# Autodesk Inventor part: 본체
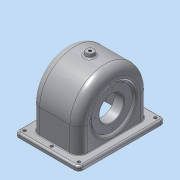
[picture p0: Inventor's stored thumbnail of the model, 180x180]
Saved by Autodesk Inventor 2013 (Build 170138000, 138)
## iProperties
Created: 2015-09
Part Number: 본체
Material: 알루미늄 6061
Document SubType Name: Modeling
Designer: dgall
Density: 1 g/cm^3
Author: dgall
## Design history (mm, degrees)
sketch "스케치1"
  geometry: L1 (-52, 70)-(52, 70); L2 (52, 70)-(52, -70); L3 (52, -70)-(-52, -70); L4 (-52, -70)-(-52, 70); 3 further points
  constraints: 8 end point, 2 midpoint, 2 parallel, 1 horizontal, 1 horizontal alignment, 1 perpendicular, 1 vertical alignment
  dimensions: "d0" = 104 distance of L1.start L1.end; "d2" = 140 distance of L1.end L2.end
extrude "돌출1" new body sketch "스케치1" distance "d3" = 7; taper "d4" = 0 deg
sketch "스케치2"
  geometry: L1 (70, 7)-(-70, 7) reference; L2 (-57, 7)-(-57, 47); L3 (57, 47)-(57, 7); L4 (-70, 0)-(70, 0) reference; A1 r 57 centre (0, 47) between (57, 47) and (-57, 47); 1 further point
  constraints: 4 end point, 2 perpendicular, 2 point on circle, 2 point on line, 2 tangent, 1 centre point, 1 vertical alignment
  dimensions: "d5" = 47 distance of point (0, 0) A1.centre; "d39" = 104 dimension on A1 L4
extrude "돌출2" join sketch "스케치2" stored distance "d7" = 77; taper "d8" = 0 deg
sketch "스케치3"
  geometry: L1 (-57, 7)-(-57, 47) reference; L2 (57, 47)-(57, 7) reference; L3 (-51, 0)-(-51, 47); L4 (51, 47)-(51, 0); L5 (-70, 0)-(70, 0) reference; A1 r 57 centre (0, 47) between (57, 47) and (-57, 47) reference; A2 r 51 centre (0, 47) between (51, 47) and (-51, 47); 1 further point
  constraints: 4 end point, 2 point on circle, 2 point on line, 1 centre point
  dimensions: "d9" = 6 radial gap between concentric circles of A2 A1; "d10" = 6 distance between parallel lines of L3 L1; "d11" = 6 distance between parallel lines of L2 L4
extrude "돌출3" cut sketch "스케치3" stored distance "d12" = 67; taper "d13" = 0 deg
sketch "스케치4"
  geometry: C1 r 31 at (47, 0); A1 r 57 centre (47, 0) between (47, -57) and (47, 57) reference; 1 further point
  constraints: 1 centre point, 1 coincident
  dimensions: "d14" = 62 diameter of C1
extrude "돌출4" join sketch "스케치4" distance "d16" = 10; taper "d17" = 0 deg
sketch "스케치6"
  geometry: C1 r 37.5 at (-47, 0); A1 r 57 centre (-47, 0) between (-47, 57) and (-47, -57) reference; 1 further point
  constraints: 1 centre point, 1 coincident
  dimensions: "d27" = 75 diameter of C1
extrude "돌출5" cut sketch "스케치6" distance "d29" = 5; taper "d30" = 0 deg
sketch "스케치7"
  geometry: L1 (-38.5, 104)-(-38.5, 47) reference; L2 (38.5, 47)-(38.5, 104) reference; L3 (-38.5, 47)-(38.5, 47); L4 (-38.5, 90.943)-(-19.5, 75); L5 (-19.5, 75)-(-19.5, 47); L6 (-35.5, 80)-(-35.5, 47); L7 (-38.5, 84.416)-(-33.237, 80); L8 (-33.237, 80)-(-35.5, 80); 1 further point
  constraints: 12 end point, 4 perpendicular, 4 point on line, 1 parallel
  dimensions: "d31" = 3 distance between parallel lines of L6 L1; "d32" = 16 distance between parallel lines of L5 L6; "d33" = 50 deg angle of L5 L4; "d34" = 56 diameter of L4.end L3; "d35" = 66 diameter of L6.start L3; "d37" = 5 distance between parallel lines of L7 L4
revolve "회전2" sketch "스케치7" stored, may be unused: angle "d36" = 90 deg
node "작업 평면1"
sketch "스케치8"
  geometry: C1 r 6 at (0, 0); 1 further point
  constraints: 1 centre point, 1 coincident
  dimensions: "d41" = 12 diameter of C1
extrude "돌출6" join sketch "스케치8" stored distance "d43" = 3; taper "d44" = 10 deg
hole "구멍1" diameter "d47" = 4.459; stored, may be unused: countersink angle "d51" = 90 deg, drill point angle "d53" = 118 deg; dims "d48" = 6, "d49" = 4, "d50" = 2, "d52" = 8, "d110" = 10, "d111" = 10
sketch "스케치9"
  geometry: C1 r 2.5 at (-44, -62); C2 r 2.5 at (0, -62); C3 r 2.5 at (44, -62); 1 further point
  constraints: 3 centre point, 2 equal radius, 2 horizontal alignment, 1 vertical alignment
  dimensions: "d54" = 62 vertical distance of C1.centre point (0, 0); "d55" = 44 distance of C1.centre C2.centre; "d56" = 44 distance of C3.centre C2.centre; "d57" = 5 diameter of C1
extrude "돌출7" cut sketch "스케치9" stored distance "d58" = 3; taper "d59" = 0 deg
sketch "스케치10"
  geometry: C1 r 33 at (0, 0) reference; 2 further points
  constraints: 1 horizontal alignment
  dimensions: "d60" = 28 distance of C1.centre point (-28, 0)
hole "구멍2" sketch "스케치10" at (-28, 0) diameter "d61" = 2.459; stored, may be unused: countersink angle "d65" = 90 deg, drill point angle "d67" = 118 deg; dims "d62" = 7, "d63" = 4, "d64" = 2, "d66" = 9
sketch "스케치11"
  geometry: C1 r 31 at (0, 0) reference; 2 further points
  constraints: 1 horizontal alignment
  dimensions: "d71" = 24 distance of point (24, 0) C1.centre
hole "구멍3" sketch "스케치11" at (24, 0) diameter "d72" = 2.459; stored, may be unused: countersink angle "d76" = 90 deg, drill point angle "d78" = 118 deg; dims "d73" = 6, "d74" = 4, "d75" = 2, "d77" = 8
hole "구멍4" diameter "d84" = 40; stored, may be unused: countersink angle "d88" = 90 deg, drill point angle "d90" = 118 deg; dims "d85" = 6, "d86" = 4, "d87" = 2, "d89" = 8, "d91" = 10, "d92" = 10
sketch "스케치12"
  geometry: L1 (77, 40)-(77, 0) reference; L2 (-13.5, 47)-(90.5, 47) reference; 2 further points
  constraints: 1 other
  dimensions: "d95" = 30 distance from line of L2 point (38.5, 17); "d96" = 38.5 distance from line of point (38.5, 17) L1
feature "엠보싱1" sketch "스케치12" dims "d0" = 104, "d2" = 140, "d97" = 0.5, "d98" = 0
fillet "모깎기1" dims "d93" = 14
fillet "모깎기2" dims "d94" = 9
fillet "모깎기3" dims "d99" = 7
fillet "모깎기4" dims "d100" = 3
fillet "모깎기5" dims "d101" = 3
fillet "모깎기6" dims "d102" = 3
fillet "모깎기7" dims "d103" = 3
fillet "모깎기8" dims "d104" = 3
fillet "모깎기9" dims "d105" = 0.5
fillet "모깎기10" dims "d106" = 1
chamfer "모따기1" distance "d107" = 1; stored, may be unused: second distance "d108" = 2, angle "d109" = 45 deg
node "솔리드1"
mirror "대칭1"
pattern_circular "원형 패턴1" dims angle "d69" = 360 deg
pattern_circular "원형 패턴2" dims angle "d80" = 360 deg
